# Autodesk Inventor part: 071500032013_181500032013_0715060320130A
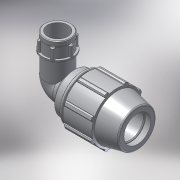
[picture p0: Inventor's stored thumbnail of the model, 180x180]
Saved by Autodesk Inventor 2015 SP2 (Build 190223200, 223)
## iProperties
Created: 2017-02
Part Number: 071500032013_181500032013_0715060320130A
Material: PVC-Piping
Description: PLASSON 90° ELBOW FEMALE ADAPTOR 32-1.1/4"
Document SubType Name: Modeling
Designer: KIM
Mass: 92.6774 g
Surface Area: 199.44 cm^2
Volume: 66.1981 cm^3
Density: 1.4 g/cm^3
Appearance: Smooth - White
Author: KIM
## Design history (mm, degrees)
derived "07150.ipt"
feature "Solid1::07150.ipt"
tag "TaggingFeature1"
body "Solid1"
other parameters: "d2" = 32, "d4" = 8.25, "d5" = 24.75, "d7" = 64, "d9" = 14.14286, "d11" = 3.3, "d13" = 120 deg, "d14" = 44.8, "d15" = 12 deg, "d16" = 55.68, "d18" = 1.6, "d19" = 35 deg, "d20" = 17.5 deg, "d21" = 59.52, "d23" = 0, "d25" = 360 deg, "d27" = 1.28, "d33" = 0.64, "d42" = 36.63, "d43" = 1.92, "d46" = 0.96, "d51" = 99, "d68" = 3.3, "d73" = 50.6376, "d74" = 25, "d75" = 58.23324, "d76" = 38.952, "d77" = 27.5, "d79" = 15.5808, "d80" = 1.16856, "d83" = 0, "d84" = 0, "d91" = 51.2, "d93" = 67, "d94" = 38.952, "d95" = 27.2664, "d96" = 9.9, "d97" = 50 deg, "d98" = 35.0568, "d99" = 0.5, "d100" = 0.5, "d101" = 8.33333, "d102" = 50.6376, "d103" = 21.25, "d104" = 0, "d108" = 360 deg, "d110" = 1.51913, "d_" = 32, "E_" = 64, "A_" = 99, "l_" = 67, "l_2" = 25, "Rp_" = 38.952, "d105" = 7.59564
